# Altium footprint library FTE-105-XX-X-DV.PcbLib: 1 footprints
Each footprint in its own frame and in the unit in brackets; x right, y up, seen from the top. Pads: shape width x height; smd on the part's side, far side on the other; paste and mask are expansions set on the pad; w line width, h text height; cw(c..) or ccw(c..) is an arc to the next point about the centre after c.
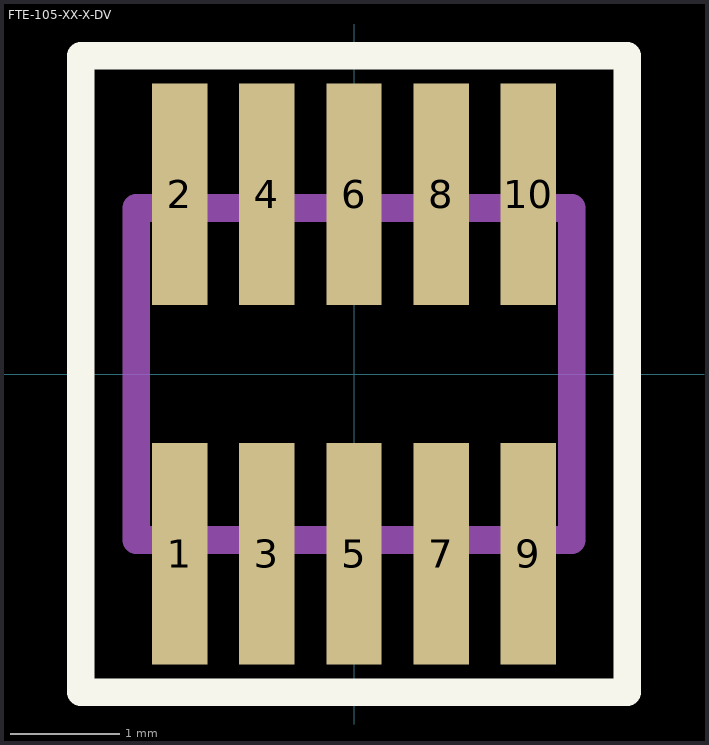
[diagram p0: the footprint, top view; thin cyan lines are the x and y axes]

## FTE-105-XX-X-DV [mil]
pads (10):
  rect 20x80 smd mask+2: 1(-63,-65) 2(-63,65) 3(-31.5,-65) 4(-31.5,65) 5(0,-65) 6(0,65) 7(31.5,-65) 8(31.5,65) 9(63,-65) 10(63,65)
Top Overlay:
  lines w10: -98.75,-115 -98.75,115 98.75,115 98.75,-115 -98.75,-115
Mechanical 1:
  lines w10: -78.75,-60 -78.75,60 78.75,60 78.75,-60 -78.75,-60
  text "J1" at -17.57,-18 h30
